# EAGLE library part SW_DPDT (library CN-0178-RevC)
(DPDT) Double Pole, Double Throw Slide Switch
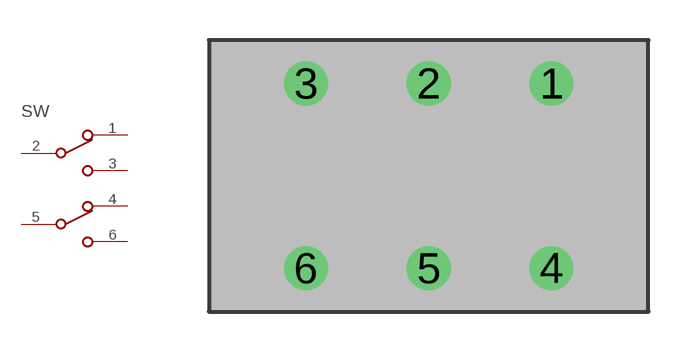
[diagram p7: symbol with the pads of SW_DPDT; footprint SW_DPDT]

Designator prefix SW

## SW_DPDT  [SW_DPDT]
1  L1  pas
2  COM  pas
3  L2  pas
4  L3  pas
5  COM2  pas
6  L4  pas

## Footprint SW_DPDT (pad centres in mm)
drill 0.635 pad 1.651 round: 1 4.597,3.454; 2 0,3.454; 3 -4.597,3.454; 4 4.597,-3.454; 5 0,-3.454; 6 -4.597,-3.454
